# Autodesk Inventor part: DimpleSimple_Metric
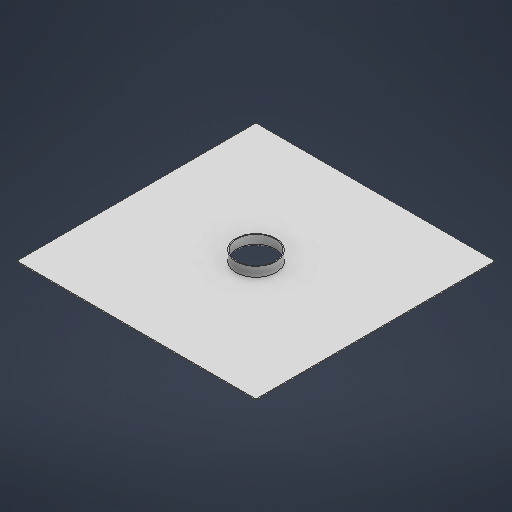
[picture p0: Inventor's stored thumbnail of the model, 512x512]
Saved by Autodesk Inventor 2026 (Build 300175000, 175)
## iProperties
Created: 2025-04
Part Number: DimpleSimple_Metric
Material: Generic
Document SubType Name: Sheet Metal
Designer: Autodesk, Inc
Density: 1 g/cm^3
Sheet Metal Rule: Default_mm
Appearance: Default
Author: Autodesk, Inc
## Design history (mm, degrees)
node "Face1"
  sketch "Sketch1"
    geometry: L1 (-63.5, 63.5)-(63.5, 63.5); L2 (63.5, 63.5)-(63.5, -63.5); L3 (63.5, -63.5)-(-63.5, -63.5); L4 (-63.5, -63.5)-(-63.5, 63.5); L5 (-63.5, 63.5)-(63.5, -63.5); L6 (63.5, 63.5)-(-63.5, -63.5); 1 further point
    constraints: 12 end point, 2 midpoint, 2 parallel, 2 perpendicular, 1 horizontal
    dimensions: "d0" = 127 distance of L1.end L2.end
sketch "Sketch2"
  geometry: C1 r 10.66 at (0, 0); C2 r 10.16 at (0, 0); 2 further points
  constraints: 3 coincident, 2 centre point
  dimensions: "diameter" = 20.32 diameter of C2; "diameterB" = 21.32 diameter of C1 (= diameter + 2 x Thickness)
extrude "Extrusion1" join sketch "Sketch2" distance "d4" = 5.58 (= Thickness + height); taper "d5" = 0 deg
extrude "Extrusion2" cut sketch "Sketch2" distance "d6" = 5.58 (= Thickness + height); taper "d7" = 0 deg
fillet "Fillet1" dims "d8" = 1 (= fillet_radius)
body "Solid1"
face "Plate1" dims "d1" = 0.5 (= Thickness)
other parameters: "Thickness" = 0.5, "BendRadius" = 0.5 (= Thickness), "BendReliefWidth" = 0.5 (= Thickness), "BendReliefDepth" = 0.25 (= 0.5 x Thickness), "CornerReliefSize" = 2 (= 4 x Thickness), "SeamGap" = 0.01, "MinimumRemnant" = 1 (= 2 x Thickness), "TransitionRadius" = 0.5 (= BendRadius), "JacobiRadiusSize" = 0.5 (= BendRadius), "GapSize" = 0.5 (= Thickness), "height" = 5.08 [user parameter; used in 2 equation terms], "fillet_radius" = 1 [user parameter; used in 1 equation term]
